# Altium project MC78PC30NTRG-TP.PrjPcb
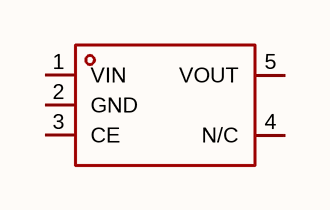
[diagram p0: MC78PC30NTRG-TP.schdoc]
1 sheet, 1 parts. Net scope: global (net labels, ports and power ports of the same name join across sheets).

## Sheet MC78PC30NTRG-TP.schdoc
size 127 x 101 mm

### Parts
U?  mc78pc30ntrg-tp  [SOT-23-5_L3.0-W1.6-P0.95-LS2.8-BR]  (value not drawn)

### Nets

Not connected (* = marked no-connect by the designer): U? 1(VIN) 2(GND) 3(CE) 4(N/C) 5(VOUT)

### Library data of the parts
U? = mc78pc30ntrg-tp: 输出极性:正极;工作电压:10V;输出电压:3V;输出电流:200mA;电源纹波抑制比(PSRR):70dB@(1kHz);输出类型:固定;; Manufacturer: TECH PUBLIC(台舟); AddInBom: yes; ModelId: 72410e292833493f86746b22636ce101; ModelTransform: 110.236,116.1415,0,0,0,0,0.002,0.001,0; Output Configuration: 正极; Voltage - Supply: 10V; Output Voltage: 3V; Output Current: 200mA; Voltage Dropout: 430mV@(100mA); standby current: 1.5uA; Output Type: 固定; Number of Outputs: 1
